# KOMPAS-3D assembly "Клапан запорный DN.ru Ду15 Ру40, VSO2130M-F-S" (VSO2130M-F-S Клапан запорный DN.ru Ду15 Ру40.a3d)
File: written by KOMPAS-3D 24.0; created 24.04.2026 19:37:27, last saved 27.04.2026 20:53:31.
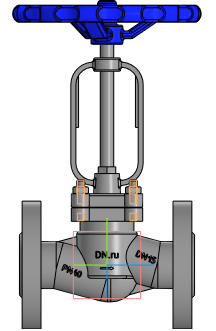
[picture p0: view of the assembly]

Document properties: Автор: DN.ru; Полное имя файла: C:\Работа\ГОТОВЫЕ ИСХОДНИКИ\VSO2130M-F-S Клапан запорный сальниковый DN.ru Ду15-100 Ру40\исходные материалы\DN15\VSO2130M-F-S Клапан запорный DN.ru Ду15 Ру40.a3d

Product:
- Component [detail]: Корпус  | qty 1  | pos. 1  | Масса: 6.9; Автор: R2D2; source file: Korpus.m3d
- Component [detail]: Деталь  | qty 1  | pos. 2  | Масса: 0.336692; Автор: mrdid; source file: rama.m3d
- Component [detail]: Деталь2  | qty 1  | pos. 3  | Масса: 0.594157; Автор: R2D2; additional columns: Типовые; source file: shturval.m3d
- Component [standard]: Шпилька М6-6gx25 ГОСТ 22032-76  | qty 4  | Масса: 0.005789; Раздел спецификации: Стандартные изделия; Рассекать на разрезах: no
- Component [standard]: Гайка М6-6H ГОСТ 5915-70  | qty 4  | Масса: 0.002573; Раздел спецификации: Стандартные изделия; Рассекать на разрезах: no
- Part/product: Клапан запорный DN.ru Ду15 Ру40  | designation VSO2130M-F-S
    Масса: 3.7
    Раздел спецификации: Прочие изделия
    Примечание: D090-01979

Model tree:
1. Контекстная связь:1  (with: Контекстная связь (Деталь):1)  (labels: Грань.Твердое тело1)
2. Контекстная связь:2  (with: Смещенная плоскость:4, Контекстная связь (Деталь):2, Грань.Элемент выдавливания:1, Грань.Элемент выдавливания:15, Грань.Элемент выдавливания:3, Грань.Элемент выдавливания:14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)  (labels: Грань.Твердое тело1; Грань.Элемент выдавливания:16.Экземпляр ( 2, 2 ); Грань.Элемент выдавливания:2.Экземпляр ( 2, 2 ); Грань.Элемент выдавливания:2.Экземпляр ( 1, 2 ))
     Угол = 9

Referenced files in C:\Работа\ГОТОВЫЕ ИСХОДНИКИ\VSO2130M-F-S Клапан запорный сальниковый DN.ru Ду15-100 Ру40\исходные материалы\DN15\: Korpus.m3d, rama.m3d, shturval.m3d
Referenced files in C:\Program Files\ASCON\KOMPAS-3D v24\Libs\PolynomLib\DATA\vault\Methods\Kompas\3D\: PLib_Stud_1_900.m3d, PLib_Nut_OST92_900.m3d
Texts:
  Крепежное изделие ГОСТ
  BOSimple***PART:e489ae6d-d315-b2e9-dd59-4407119351be***SHORTLOC:Root±30±20±10±120±10±20[Нет;Без покрытия;Без указания материала;-;6;25;1;1]
  BOSimple***PART:832b7c99-94b5-75d7-382c-73b3a2f1c6df***SHORTLOC:Root±30±10±20±©{}110±10±50±60[Нет;Без покрытия;Без указания материала;-;6;1;10]
  Программные изделия  и базы данных
  VSO2130M-F-S
  Деталь2 Деталь2
  Шпилька М6-6gx25 ГОСТ 22032-76 (1)
  cut1
  Шпилька М6-6gx25 ГОСТ 22032-76 (2)
  Шпилька М6-6gx25 ГОСТ 22032-76 (3)
  Шпилька М6-6gx25 ГОСТ 22032-76 (4)
  Гайка М6-6H ГОСТ 5915-70 (1)
  bcut1
  hole1
  hcut1
  hole2
  Гайка М6-6H ГОСТ 5915-70 (2)
  Гайка М6-6H ГОСТ 5915-70 (3)
  Гайка М6-6H ГОСТ 5915-70 (4)
  Грань.Элемент выдавливания:2.Экземпляр ( 2, 1 )
  Plane. Начало координат
  Плоскость ZX.Начало координат
  Плоскость XY.Начало координат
